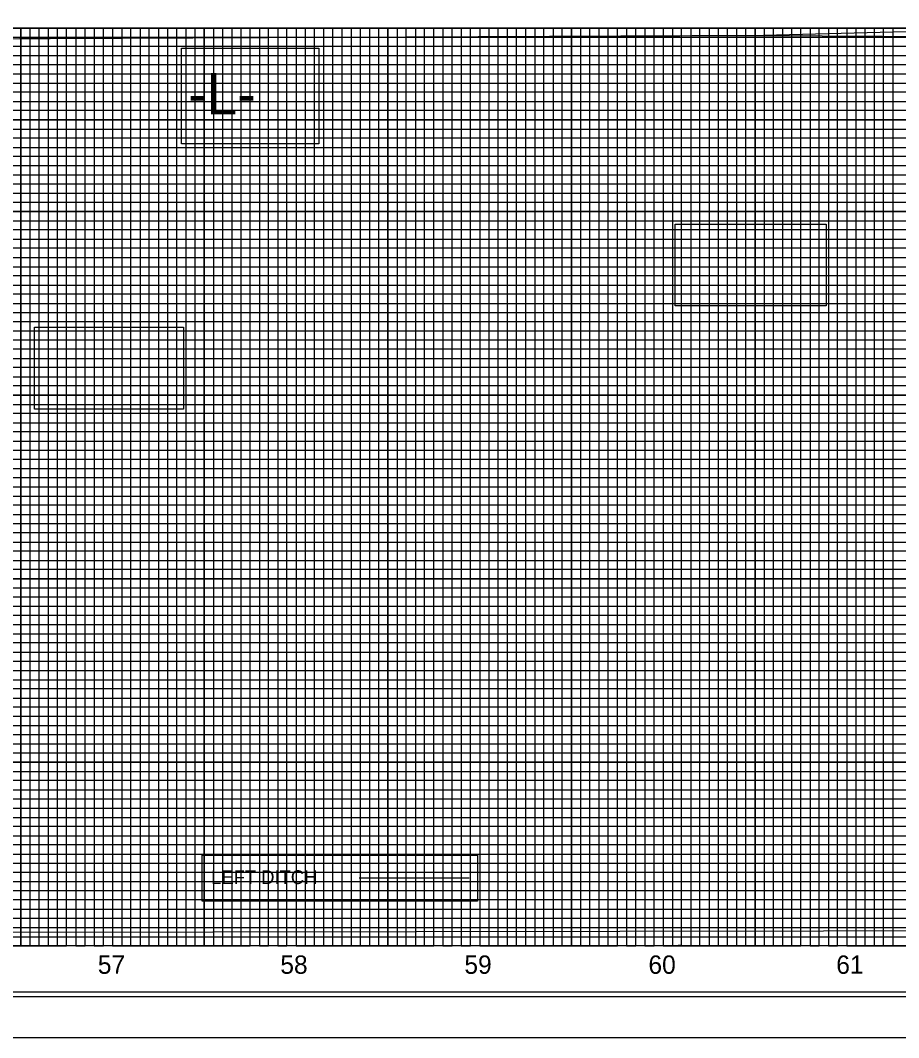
# Model space of a CAD drawing. Extents: x 557032 to 562069, y 513430 to 515874.
# Drawn here: x 557699 to 558178, y 514774 to 515328 of the extents above; entities that cross this region are included whole.
import ezdxf

# ---------------------------------------------------------------- set-up
doc = ezdxf.new("R2010")
doc.units = 0
for name, color, linetype in [('Exist Vertical Profile Horizontal Axis Label Major', 7, 'Continuous'), ('Prop Grid Mask', 7, 'Continuous'), ('Prop PFL Ditch Label CELL', 7, 'Continuous'), ('Prop Vertical Profile Curve Label', 7, 'Continuous'), ('Prop VPI Label', 7, 'Continuous'), ('Scratch_Level_5', 7, 'Continuous'), ('Sheet Cutting Line CELL', 7, 'Continuous'), ('Sheet DOT Grid CELL', 7, 'Continuous'), ('Sheet Layout Profile Border Port 2', 7, 'Continuous'), ('Sheet Plot Border Inside CELL', 7, 'Continuous'), ('Sheet Plot Border Outside CELL', 7, 'Continuous'), ('Sheet Profile CELL', 7, 'Continuous'), ('Sheet Profile Grid Major CELL', 7, 'Continuous'), ('Sheet Profile Grid Middle CELL', 7, 'Continuous'), ('Sheet Profile Grid Minor CELL', 7, 'Continuous')]:
    doc.layers.add(name, color=color, linetype=linetype)

msp = doc.modelspace()

# ---------------------------------------------------------------- linework, layer by layer
at = {"layer": 'Prop Grid Mask'}
msp.add_lwpolyline([(557798.19, 514873.67), (557948.19, 514873.67), (557948.19, 514848.67), (557798.19, 514848.67)], close=True, dxfattribs=at)
at = {"layer": 'Prop PFL Ditch Label CELL'}
msp.add_line((557883.74, 514861.37), (557943.74, 514861.37), dxfattribs=at)
at = {"layer": 'Prop Vertical Profile Curve Label'}
for points in [[(557787.1, 515313.24), (557861.87, 515313.24), (557861.87, 515261.29), (557787.1, 515261.29)], [(557787.1, 515313.24), (557861.87, 515313.24), (557861.87, 515261.29), (557787.1, 515261.29)], [(558055.93, 515217.53), (558138.24, 515217.53), (558138.24, 515173.03), (558055.93, 515173.03)], [(557706.86, 515161.4), (557788.08, 515161.4), (557788.08, 515116.66), (557706.86, 515116.66)]]:
    msp.add_lwpolyline(points, close=True, dxfattribs=at)
at = {"layer": 'Prop VPI Label'}
for points in [[(557787.1, 515313.24), (557861.87, 515313.24), (557861.87, 515261.29), (557787.1, 515261.29)], [(557798.19, 514873.67), (557948.19, 514873.67), (557948.19, 514848.67), (557798.19, 514848.67)]]:
    msp.add_lwpolyline(points, close=True, dxfattribs=at)
at = {"layer": 'Scratch_Level_5'}
for points in [[(558499.4, 515824.23), (557249.45, 515849.28), (557249.45, 515349.28), (557236.61, 515332.67), (557249.45, 515324.28), (558649.45, 515324.28), (558662.72, 515334.01), (558649.45, 515349.28), (558649.45, 515688.23), (558499.4, 515688.23)], [(557249.45, 515324.28), (557249.45, 514824.28), (557239, 514812.71), (557236.95, 514799.28), (558647.93, 514799.13), (558699.45, 514799.28), (558649.45, 514824.28), (558649.45, 515324.28)]]:
    msp.add_lwpolyline(points, close=True, dxfattribs=at)
for points in [[(558650.22, 515320.39), (558430.88, 515318.37), (558259.45, 515324.28), (558104.05, 515320.21), (557248.74, 515316.3)], [(557250.22, 514849.46), (558648.7, 514849.31), (558650.22, 514849.32)]]:
    msp.add_lwpolyline(points, dxfattribs=at)
at = {"layer": 'Sheet Cutting Line CELL'}
msp.add_line((557032.45, 514774.28), (558716.45, 514774.28), dxfattribs=at)
at = {"layer": 'Sheet DOT Grid CELL'}
for p, q in [((557199.45, 515324.28), (558699.34, 515324.28)), ((557699.45, 515324.28), (557699.45, 514824.28)), ((557749.45, 515324.28), (557749.45, 514824.28)), ((557799.45, 515324.28), (557799.45, 514824.28)), ((557849.45, 515324.28), (557849.45, 514824.28)), ((557899.45, 515324.28), (557899.45, 514824.28)), ((557949.45, 515324.28), (557949.45, 514824.28)), ((557999.45, 515324.28), (557999.45, 514824.28)), ((558049.45, 515324.28), (558049.45, 514824.28)), ((558099.45, 515324.28), (558099.45, 514824.28)), ((558149.45, 515324.28), (558149.45, 514824.28)), ((557199.45, 515274.28), (558699.34, 515274.28)), ((557199.45, 515224.28), (558699.34, 515224.28)), ((557199.45, 515174.28), (558699.34, 515174.28)), ((557199.45, 515124.28), (558699.34, 515124.28)), ((557199.45, 515074.28), (558699.34, 515074.28)), ((557199.45, 515024.28), (558699.34, 515024.28)), ((557199.45, 514974.28), (558699.34, 514974.28)), ((557199.45, 514924.28), (558699.34, 514924.28)), ((557199.45, 514874.28), (558699.34, 514874.28))]:
    msp.add_line(p, q, dxfattribs=at)
at = {"layer": 'Sheet Layout Profile Border Port 2'}
msp.add_lwpolyline([(557249.45, 515324.28), (558649.45, 515324.28), (558649.45, 514824.28), (557249.45, 514824.28)], close=True, dxfattribs=at)
for points in [[(558649.45, 515320.22), (558430.11, 515318.19), (558103.28, 515320.04), (557249.45, 515316.52)], [(557249.45, 514831.1), (558358.41, 514832.88), (558649.45, 514833.95)]]:
    msp.add_lwpolyline(points, dxfattribs=at)
at = {"layer": 'Sheet Plot Border Inside CELL'}
msp.add_lwpolyline([(557045.45, 514796.73), (558711.95, 514796.73), (558711.95, 515851.83), (557045.45, 515851.83)], close=True, dxfattribs=at)
at = {"layer": 'Sheet Plot Border Outside CELL'}
msp.add_lwpolyline([(557032.45, 514774.28), (558716.45, 514774.28), (558716.45, 515874.28), (557032.45, 515874.28)], close=True, dxfattribs=at)
at = {"layer": 'Sheet Profile CELL'}
for p, q in [((557199.45, 515324.28), (558699.45, 515324.28)), ((558699.45, 514824.28), (557199.45, 514824.28)), ((557199.45, 514799.28), (558699.45, 514799.28))]:
    msp.add_line(p, q, dxfattribs=at)
msp.add_lwpolyline([(558699.45, 515849.28), (557199.45, 515849.28), (557199.45, 514799.28), (558699.45, 514799.28)], close=True, dxfattribs=at)
at = {"layer": 'Sheet Profile Grid Major CELL'}
for p, q in [((557699.45, 515324.28), (557749.45, 515324.28)), ((557799.45, 515324.28), (557849.45, 515324.28)), ((557899.45, 515324.28), (557949.45, 515324.28)), ((557999.45, 515324.28), (558049.45, 515324.28)), ((558099.45, 515324.28), (558149.45, 515324.28))]:
    msp.add_line(p, q, dxfattribs=at)
for points in [[(557649.45, 514824.28), (557699.45, 514824.28), (557699.45, 515324.28), (557749.45, 515324.28), (557749.45, 514824.28), (557799.45, 514824.28), (557799.45, 515324.28), (557849.45, 515324.28), (557849.45, 514824.28), (557899.45, 514824.28), (557899.45, 515324.28), (557949.45, 515324.28), (557949.45, 514824.28), (557999.45, 514824.28), (557999.45, 515324.28), (558049.45, 515324.28), (558049.45, 514824.28), (558099.45, 514824.28), (558099.45, 515324.28), (558149.45, 515324.28), (558149.45, 514824.28), (558199.45, 514824.28)], [(558699.45, 515274.28), (557199.45, 515274.28)], [(558699.45, 515224.28), (557199.45, 515224.28), (557199.45, 515174.28), (558699.45, 515174.28)], [(558699.45, 515124.28), (557199.45, 515124.28), (557199.45, 515074.28), (558699.45, 515074.28)], [(558699.45, 515024.28), (557199.45, 515024.28), (557199.45, 514974.28), (558554.45, 514974.28)], [(558699.45, 514924.28), (557199.45, 514924.28), (557199.45, 514924.28), (557199.45, 514874.28), (558699.45, 514874.28)], [(558699.45, 514824.28), (557199.45, 514824.28)]]:
    msp.add_lwpolyline(points, dxfattribs=at)
at = {"layer": 'Sheet Profile Grid Middle CELL'}
for points in [[(557674.45, 514824.28), (557724.45, 514824.28), (557724.45, 515324.28), (557774.45, 515324.28), (557774.45, 514824.28), (557824.45, 514824.28), (557824.45, 514824.28), (557824.45, 515324.28), (557874.45, 515324.28), (557874.45, 514824.28), (557924.45, 514824.28), (557924.45, 515324.28), (557974.45, 515324.28), (557974.45, 514824.28), (558024.45, 514824.28), (558024.45, 515324.28), (558074.45, 515324.28), (558074.45, 514824.28), (558124.45, 514824.28), (558124.45, 515324.28), (558174.45, 515324.28), (558174.45, 514824.28), (558224.45, 514824.28)], [(557199.45, 515299.28), (558699.45, 515299.28)], [(558699.45, 515249.28), (557199.45, 515249.28), (557199.45, 515199.28), (558699.45, 515199.28)], [(558699.45, 515149.28), (557199.45, 515149.28), (557199.45, 515099.28), (558699.45, 515099.28)], [(558699.45, 515049.28), (557199.45, 515049.28), (557199.45, 514999.28), (558699.45, 514999.28)], [(558699.45, 514949.28), (557199.45, 514949.28), (557199.45, 514899.28), (558699.45, 514899.28)], [(558699.45, 514849.28), (557199.45, 514849.28)]]:
    msp.add_lwpolyline(points, dxfattribs=at)
at = {"layer": 'Sheet Profile Grid Minor CELL'}
for p, q in [((557249.45, 515319.28), (558649.45, 515319.28)), ((558649.45, 515314.28), (557249.45, 515314.28)), ((557249.45, 515309.28), (558649.45, 515309.28)), ((558649.45, 515304.28), (557249.45, 515304.28)), ((557249.45, 515294.28), (558649.45, 515294.28)), ((558649.45, 515289.28), (557249.45, 515289.28)), ((557249.45, 515284.28), (558649.45, 515284.28)), ((558649.45, 515279.28), (557249.45, 515279.28)), ((557249.45, 515269.28), (558649.45, 515269.28)), ((558649.45, 515264.28), (557249.45, 515264.28)), ((557249.45, 515259.28), (558649.45, 515259.28)), ((558649.45, 515254.28), (557249.45, 515254.28)), ((557249.45, 515244.28), (558649.45, 515244.28)), ((558649.45, 515239.28), (557249.45, 515239.28)), ((557249.45, 515234.28), (558649.45, 515234.28)), ((558649.45, 515229.28), (557249.45, 515229.28)), ((557249.45, 515219.28), (558649.45, 515219.28)), ((558649.45, 515214.28), (557249.45, 515214.28)), ((557249.45, 515209.28), (558649.45, 515209.28)), ((558649.45, 515204.28), (557249.45, 515204.28)), ((557249.45, 515194.28), (558649.45, 515194.28)), ((558649.45, 515189.28), (557249.45, 515189.28)), ((557249.45, 515184.28), (558649.45, 515184.28)), ((558649.45, 515179.28), (557249.45, 515179.28)), ((557249.45, 515169.28), (558649.45, 515169.28)), ((558649.45, 515164.28), (557249.45, 515164.28)), ((557249.45, 515159.28), (558649.45, 515159.28)), ((558649.45, 515154.28), (557249.45, 515154.28)), ((557249.45, 515144.28), (558649.45, 515144.28)), ((558649.45, 515139.28), (557249.45, 515139.28)), ((557249.45, 515134.28), (558649.45, 515134.28)), ((558649.45, 515129.28), (557249.45, 515129.43)), ((557249.45, 515119.28), (558649.45, 515119.28)), ((558649.45, 515114.28), (557249.45, 515114.28)), ((557249.45, 515109.28), (558649.45, 515109.28)), ((558649.45, 515104.28), (557249.45, 515104.28)), ((557249.45, 515094.28), (558649.45, 515094.28)), ((558649.45, 515089.28), (557249.45, 515089.28)), ((557249.45, 515084.28), (558649.45, 515084.28)), ((558649.45, 515079.28), (557249.45, 515079.28)), ((557249.45, 515069.28), (558649.45, 515069.28)), ((558649.45, 515064.28), (557249.45, 515064.28)), ((557249.45, 515059.28), (558649.45, 515059.28)), ((558649.45, 515054.28), (557249.45, 515054.28)), ((557249.45, 515044.28), (558649.45, 515044.28)), ((558649.45, 515039.28), (557249.45, 515039.28)), ((557249.45, 515034.28), (558649.45, 515034.28)), ((558649.45, 515029.28), (557249.45, 515029.28)), ((557249.45, 515019.28), (558649.45, 515019.28)), ((558649.45, 515014.28), (557249.45, 515014.28)), ((557249.45, 515009.28), (558649.45, 515009.28)), ((558649.45, 515004.28), (557249.45, 515004.28)), ((557249.45, 514994.28), (558649.45, 514994.28)), ((558554.45, 514989.28), (557249.45, 514989.28)), ((557249.45, 514984.28), (558554.45, 514984.28)), ((558554.45, 514979.28), (557249.45, 514979.28)), ((557249.45, 514969.28), (558554.45, 514969.28)), ((558649.45, 514964.28), (557249.45, 514964.28)), ((557249.45, 514959.28), (558649.45, 514959.28)), ((558649.45, 514954.28), (557249.45, 514954.28)), ((557249.45, 514944.28), (558649.45, 514944.28)), ((558649.45, 514939.28), (557249.45, 514939.28)), ((557249.45, 514934.28), (558649.45, 514934.28)), ((558649.45, 514929.28), (557249.45, 514929.28)), ((557249.45, 514919.28), (558649.45, 514919.28)), ((558649.45, 514914.28), (557249.45, 514914.28)), ((557249.45, 514909.28), (558649.45, 514909.28)), ((558649.45, 514904.28), (557249.45, 514904.28)), ((557249.45, 514894.28), (558649.45, 514894.28)), ((558649.45, 514889.28), (557249.45, 514889.28)), ((557249.45, 514884.28), (558649.45, 514884.28)), ((558649.45, 514879.28), (557249.45, 514879.28)), ((557249.45, 514869.28), (558649.45, 514869.28)), ((558649.45, 514864.28), (557249.45, 514864.28)), ((557249.45, 514859.28), (558649.45, 514859.28)), ((558649.45, 514854.28), (557249.45, 514854.28)), ((557249.45, 514844.28), (558649.45, 514844.28)), ((558649.45, 514839.28), (557249.45, 514839.28)), ((557249.45, 514834.28), (558649.45, 514834.28)), ((557249.45, 514829.28), (558649.45, 514829.28))]:
    msp.add_line(p, q, dxfattribs=at)
for points in [[(557694.45, 515324.28), (557704.45, 515324.28), (557704.45, 514824.28), (557709.45, 514824.28), (557709.45, 515324.28), (557714.45, 515324.28), (557714.45, 514824.28), (557719.45, 514824.28), (557719.45, 515324.28), (557729.45, 515324.28), (557729.45, 514824.28), (557734.45, 514824.28), (557734.45, 515324.28), (557739.45, 515324.28), (557739.45, 514824.28), (557744.45, 514824.28), (557744.45, 515324.28), (557754.45, 515324.28), (557754.45, 514824.28), (557759.45, 514824.28), (557759.45, 515324.28), (557764.45, 515324.28), (557764.45, 514824.28), (557769.45, 514824.28), (557769.45, 515324.28), (557779.45, 515324.28)], [(557779.45, 515324.28), (557779.45, 514824.28), (557784.45, 514824.28), (557784.45, 515324.28), (557789.45, 515324.28), (557789.45, 514824.28), (557794.45, 514824.28), (557794.45, 515324.28), (557804.45, 515324.28), (557804.45, 514824.28), (557809.45, 514824.28), (557809.45, 515324.28), (557814.45, 515324.28), (557814.45, 514824.28), (557819.45, 514824.28), (557819.45, 515324.28), (557829.45, 515324.28), (557829.45, 514824.28), (557834.45, 514824.28), (557834.45, 515324.28), (557839.45, 515324.28), (557839.45, 514824.28), (557844.45, 514824.28), (557844.45, 515324.28), (557854.45, 515324.28), (557854.45, 514824.28), (557859.45, 514824.28), (557859.45, 515324.28), (557864.45, 515324.28), (557864.45, 514824.28), (557869.45, 514824.28), (557869.45, 515324.28), (557879.45, 515324.28), (557879.45, 514824.28), (557884.45, 514824.28), (557884.45, 515324.28), (557889.45, 515324.28), (557889.45, 514824.28), (557894.45, 514824.28), (557894.45, 515324.28), (557904.45, 515324.28), (557904.45, 514824.28), (557904.45, 514824.28), (557909.45, 514824.28), (557909.45, 515324.28), (557914.45, 515324.28), (557914.45, 514824.28), (557919.45, 514824.28), (557919.45, 515324.28), (557929.45, 515324.28), (557929.45, 514824.28), (557934.45, 514824.28), (557934.45, 515324.28), (557939.45, 515324.28), (557939.45, 514824.28), (557944.45, 514824.28), (557944.45, 515324.28), (557954.45, 515324.28), (557954.45, 514824.28), (557959.45, 514824.28), (557959.45, 515324.28), (557964.45, 515324.28), (557964.45, 514824.28), (557969.45, 514824.28), (557969.45, 515324.28), (557979.45, 515324.28), (557979.45, 514824.28), (557984.45, 514824.28), (557984.45, 515324.28), (557989.45, 515324.28), (557989.45, 514824.28), (557994.45, 514824.28), (557994.45, 515324.28), (558004.45, 515324.28), (558004.45, 514824.28), (558009.45, 514824.28), (558009.45, 515324.28), (558014.45, 515324.28), (558014.45, 514824.28), (558019.45, 514824.28), (558019.45, 515324.28), (558029.45, 515324.28), (558029.45, 514824.28), (558034.45, 514824.28), (558034.45, 515324.28), (558039.45, 515324.28), (558039.45, 514824.28), (558044.45, 514824.28), (558044.45, 515324.28), (558054.45, 515324.28), (558054.45, 514824.28), (558059.15, 514824.83), (558059.45, 514824.28), (558059.45, 515324.28), (558064.45, 515324.28), (558064.45, 514824.28), (558069.45, 514824.28), (558069.45, 515324.28), (558079.45, 515324.28), (558079.45, 514824.28), (558084.45, 514824.28)], [(558084.45, 514824.28), (558084.45, 515324.28), (558089.45, 515324.28), (558089.45, 514824.28), (558094.45, 514824.28), (558094.45, 515324.28), (558104.45, 515324.28), (558104.45, 514824.28), (558109.45, 514824.28), (558109.45, 515324.28), (558114.45, 515324.28), (558114.45, 514824.28), (558119.45, 514824.28), (558119.45, 515324.28), (558129.45, 515324.28), (558129.45, 514824.28), (558134.45, 514824.28), (558134.45, 515324.28), (558139.45, 515324.28), (558139.45, 514824.28), (558144.45, 514824.28), (558144.45, 515324.28), (558154.45, 515324.28), (558154.45, 514824.28), (558159.45, 514824.28), (558159.45, 515324.28), (558164.45, 515324.28), (558164.45, 514824.28), (558169.45, 514824.28), (558169.45, 515324.28), (558179.45, 515324.28)]]:
    msp.add_lwpolyline(points, dxfattribs=at)

# ---------------------------------------------------------------- texts
at = {"layer": 'Exist Vertical Profile Horizontal Axis Label Major'}
for s, p in [('57', (557741.42, 514809.06)), ('58', (557840.85, 514809.06)), ('59', (557941.13, 514809.06)), ('60', (558041.4, 514809.06)), ('61', (558143.72, 514809.06))]:
    msp.add_text(s, height=10, dxfattribs=at).set_placement(p)
at = {"layer": 'Prop PFL Ditch Label CELL'}
msp.add_text('LEFT DITCH', height=7.485, dxfattribs=at).set_placement((557803.19, 514857.97))
at = {"layer": 'Prop Vertical Profile Curve Label'}
msp.add_text('-L-', height=22.5, dxfattribs=at).set_placement((557790.67, 515277.25))

doc.saveas('drawing.dxf')
